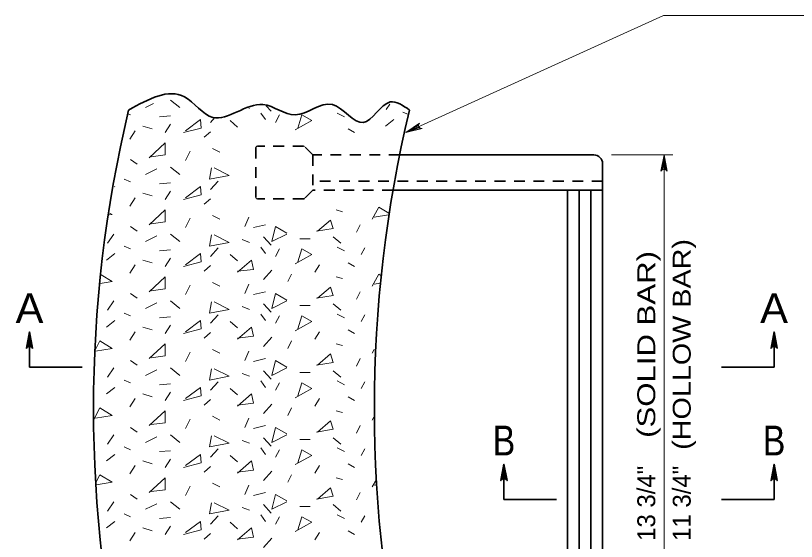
# Model space of a CAD drawing. Extents: x 16 to 133, y -56 to 112.
# Drawn here: x 17.77 to 62.26, y 81.71 to 111.64 of the extents above; entities that cross this region are included whole.
import ezdxf
from ezdxf.enums import TextEntityAlignment as Align

# ---------------------------------------------------------------- set-up
doc = ezdxf.new("R2010")
doc.units = 0
doc.header["$LTSCALE"] = 0.41
doc.linetypes.add('SHORT_DASHED', pattern=[2.7, 1.5, -1.2])
for name, color, linetype, lineweight in [('1', 7, 'Continuous', 35), ('10', 7, 'Continuous', 13), ('12', 7, 'Continuous', 53), ('13', 7, 'Continuous', 25), ('6', 7, 'Continuous', 13)]:
    doc.layers.add(name, color=color, linetype=linetype, lineweight=lineweight)

msp = doc.modelspace()

# ---------------------------------------------------------------- linework, layer by layer
at = {"layer": '1', "linetype": 'SHORT_DASHED'}
for p, q in [((31.4632, 104.126), (31.4632, 101.2927)), ((34.1786, 104.2094), (31.5465, 104.2094)), ((34.7132, 103.7094), (34.2376, 104.185)), ((34.7132, 103.7094), (34.7132, 101.7094)), ((39.651, 103.7094), (34.7132, 103.7094)), ((51.2132, 102.2094), (34.7132, 102.2094)), ((34.7132, 101.7094), (34.2376, 101.2338)), ((39.2776, 101.7094), (34.7132, 101.7094)), ((34.1786, 101.2094), (31.5465, 101.2094))]:
    msp.add_line(p, q, dxfattribs=at)
at = {"layer": '1'}
for p, q in [((50.7132, 103.7094), (39.651, 103.7094)), ((51.2132, 76.2094), (51.2132, 103.2094)), ((51.2132, 101.7094), (39.2776, 101.7094)), ((49.2132, 77.7094), (49.2132, 101.7094)), ((49.8798, 77.7094), (49.8798, 101.7094)), ((50.5465, 77.7094), (50.5465, 101.7094))]:
    msp.add_line(p, q, dxfattribs=at)
for centre, radius, start, end in [((95.4632, 89.267), 73.25, 166.58032, 193.41967), ((111.4632, 89.267), 73.25, 166.58032, 193.41967), ((50.7132, 103.2094), 0.5, 0, 90)]:
    msp.add_arc(centre, radius, start, end, dxfattribs=at)
at = {"layer": '1', "linetype": 'SHORT_DASHED'}
msp.add_arc((34.1787, 101.2927), 0.0833, 270, 315, dxfattribs=at)
at = {"layer": '1'}
msp.add_spline([(24.2131, 106.267), (27.3964, 107.0185), (29.0086, 105.8453), (31.8666, 106.5785), (33.6986, 105.9919), (35.8238, 106.5785), (37.5826, 105.552), (39.1216, 106.7252), (40.2131, 106.267)], degree=3, dxfattribs=at)
at = {"layer": '10'}
for p, q in [((54.6853, 111.6433), (40.0105, 104.9805)), ((67.387, 111.6433), (54.6853, 111.6433)), ((51.7132, 103.7094), (55.2132, 103.7094)), ((54.7132, 75.7094), (54.7132, 103.7094))]:
    msp.add_line(p, q, dxfattribs=at)
at = {"layer": '10', "lineweight": 35}
for p, q in [((60.9837, 91.6335), (60.9837, 93.6335)), ((57.9837, 91.6335), (60.9837, 91.6335))]:
    msp.add_line(p, q, dxfattribs=at)
at = {"layer": '10'}
for points in [[(40.0105, 104.9805), (40.7869, 105.5249), (40.7421, 105.4499), (40.7342, 105.3777), (40.7503, 105.3164), (40.7859, 105.2639), (40.8455, 105.2223), (40.9314, 105.2067), (40.0105, 104.9805), (40.8455, 105.2223), (40.7859, 105.2639), (40.0105, 104.9805), (40.7503, 105.3164), (40.7342, 105.3777), (40.0105, 104.9805), (40.7421, 105.4499)], [(54.7132, 103.7094), (54.8879, 102.7773), (54.8382, 102.8491), (54.7757, 102.8861), (54.7132, 102.8969), (54.6507, 102.8861), (54.5882, 102.8491), (54.5384, 102.7773), (54.7132, 103.7094), (54.5882, 102.8491), (54.6507, 102.8861), (54.7132, 103.7094), (54.7132, 102.8969), (54.7757, 102.8861), (54.7132, 103.7094), (54.8382, 102.8491)]]:
    msp.add_lwpolyline(points, dxfattribs=at)
at = {"layer": '10', "lineweight": 35}
for points in [[(18.5662, 93.6335), (18.3915, 92.7014), (18.4412, 92.7733), (18.5037, 92.8103), (18.5662, 92.821), (18.6287, 92.8103), (18.6912, 92.7733), (18.741, 92.7014), (18.5662, 93.6335), (18.6912, 92.7733), (18.6287, 92.8103), (18.5662, 93.6335), (18.5662, 92.821), (18.5037, 92.8103), (18.5662, 93.6335), (18.4412, 92.7733)], [(21.5662, 91.6335), (18.5662, 91.6335), (18.5662, 93.6335)], [(60.9837, 93.6335), (61.1585, 92.7014), (61.1087, 92.7733), (61.0462, 92.8103), (60.9837, 92.821), (60.9212, 92.8103), (60.8587, 92.7733), (60.809, 92.7014), (60.9837, 93.6335), (60.8587, 92.7733), (60.9212, 92.8103), (60.9837, 93.6335), (60.9837, 92.821), (61.0462, 92.8103), (60.9837, 93.6335), (61.1087, 92.7733)], [(45.5961, 86.0975), (45.4214, 85.1654), (45.4711, 85.2373), (45.5336, 85.2743), (45.5961, 85.285), (45.6586, 85.2743), (45.7211, 85.2373), (45.7709, 85.1654), (45.5961, 86.0975), (45.7211, 85.2373), (45.6586, 85.2743), (45.5961, 86.0975), (45.5961, 85.285), (45.5336, 85.2743), (45.5961, 86.0975), (45.4711, 85.2373)], [(48.5961, 84.0975), (45.5961, 84.0975), (45.5961, 86.0975)], [(57.9837, 84.0975), (60.9837, 84.0975), (60.9837, 86.0975)], [(60.9837, 86.0975), (61.1585, 85.1654), (61.1087, 85.2373), (61.0462, 85.2743), (60.9837, 85.285), (60.9212, 85.2743), (60.8587, 85.2373), (60.809, 85.1654), (60.9837, 86.0975), (60.8587, 85.2373), (60.9212, 85.2743), (60.9837, 86.0975), (60.9837, 85.285), (61.0462, 85.2743), (60.9837, 86.0975), (61.1087, 85.2373)]]:
    msp.add_lwpolyline(points, dxfattribs=at)
at = {"layer": '6'}
for p, q in [((26.6059, 106.8326), (27.1354, 106.409)), ((25.6384, 106.6401), (25.1762, 106.409)), ((31.0526, 106.3764), (31.1067, 106.3561)), ((32.0547, 106.5009), (32.3246, 106.1972)), ((36.1245, 106.4531), (36.296, 106.3031)), ((36.1245, 106.4531), (36.1245, 106.4531)), ((39.0999, 106.6021), (38.8906, 106.3031)), ((24.1736, 106.052), (24.329, 105.9854)), ((25.9704, 105.8795), (26.6059, 105.9325)), ((31.7421, 106.0913), (32.0069, 105.7207)), ((32.8012, 105.9854), (32.5894, 105.5618)), ((36.0841, 106.0913), (36.5078, 105.8795)), ((39.8437, 106.1443), (40.1567, 106.0101)), ((26.2881, 104.9793), (26.6059, 105.4559)), ((28.8828, 105.5618), (29.129, 105.8388)), ((29.9947, 105.6677), (30.4184, 105.2971)), ((39.3142, 105.7207), (38.8376, 105.35)), ((24.5937, 105.0852), (24.276, 104.6087)), ((25.0173, 105.35), (25.5468, 105.1911)), ((28.5121, 104.7146), (28.8828, 105.0323)), ((36.7196, 105.1911), (37.0902, 104.9793)), ((27.4531, 103.3908), (27.7178, 103.9203)), ((28.9887, 104.0792), (29.4123, 103.8674)), ((24.329, 103.4437), (24.6996, 103.179)), ((25.8116, 102.9142), (25.1762, 102.5965)), ((26.6059, 103.0201), (27.1354, 102.5965)), ((23.9583, 102.3318), (24.329, 102.1729)), ((23.4288, 101.9082), (23.4074, 101.8915)), ((25.9704, 102.067), (26.6059, 102.12)), ((28.8828, 101.7493), (29.3064, 102.2259)), ((25.0173, 101.5375), (25.5468, 101.3786)), ((26.2881, 101.1668), (26.6059, 101.6434)), ((24.5937, 101.2727), (24.276, 100.7962)), ((28.5121, 100.9021), (28.8828, 101.2198)), ((36.0312, 100.5844), (36.4019, 100.4785)), ((27.4531, 99.5783), (27.7178, 100.1078)), ((28.9887, 100.2667), (29.4123, 100.0549)), ((31.0538, 100.1608), (30.842, 99.6312)), ((39.0151, 100.2962), (38.2022, 100.1608)), ((32.0069, 99.7372), (31.3185, 99.5783)), ((37.1961, 99.3135), (37.4079, 99.7372)), ((23.3758, 99.2076), (23.0052, 98.6781)), ((24.329, 99.6312), (24.6996, 99.3665)), ((26.6059, 99.2076), (27.1354, 98.784)), ((25.8116, 99.1017), (25.1762, 98.784)), ((30.6831, 98.8899), (31.1067, 98.7311)), ((31.901, 99.0488), (32.3246, 98.5722)), ((33.9661, 98.9429), (34.5486, 98.9429)), ((35.8724, 99.0488), (36.296, 98.6781)), ((23.9583, 98.5193), (24.329, 98.3604)), ((25.9704, 98.2545), (26.6059, 98.3075)), ((28.8828, 97.9368), (29.3064, 98.4134)), ((31.7421, 98.4663), (32.0069, 98.0957)), ((32.8012, 98.3604), (32.5894, 97.9368)), ((36.0841, 98.4663), (36.5078, 98.2545)), ((37.4609, 98.0427), (37.6727, 98.4134)), ((23.4288, 98.0957), (22.9522, 97.725)), ((29.9947, 98.0427), (30.4184, 97.6721)), ((24.5937, 97.4602), (24.276, 96.9837)), ((25.0173, 97.725), (25.5468, 97.5661)), ((26.2881, 97.3543), (26.6059, 97.8309)), ((34.8133, 97.0366), (35.0781, 97.4602)), ((36.7196, 97.5661), (37.0902, 97.3543)), ((28.5121, 97.0896), (28.8828, 97.4073)), ((32.3776, 97.1425), (31.901, 96.613)), ((33.4895, 96.9307), (33.2777, 96.5071)), ((36.0312, 96.7719), (36.4019, 96.666)), ((27.4531, 95.7658), (27.7178, 96.2953)), ((28.9887, 96.4542), (29.4123, 96.2424)), ((31.0538, 96.3483), (30.842, 95.8187)), ((38.5482, 96.4059), (38.2022, 96.3483)), ((24.329, 95.8187), (24.6996, 95.554)), ((32.0069, 95.9247), (31.3185, 95.7658)), ((37.1961, 95.501), (37.4079, 95.9247)), ((23.3758, 95.3951), (23.0052, 94.8656)), ((25.8116, 95.2892), (25.1762, 94.9715)), ((26.6059, 95.3951), (27.1354, 94.9715)), ((31.901, 95.2363), (32.3246, 94.7597)), ((35.8724, 95.2363), (36.296, 94.8656)), ((30.6831, 95.0774), (31.1067, 94.9186)), ((33.9661, 95.1304), (34.5486, 95.1304)), ((23.9583, 94.7068), (24.329, 94.5479)), ((25.9704, 94.442), (26.6059, 94.495)), ((28.8828, 94.1243), (29.3064, 94.6009)), ((31.7421, 94.6538), (32.0069, 94.2832)), ((32.8012, 94.5479), (32.5894, 94.1243)), ((36.0841, 94.6538), (36.5078, 94.442)), ((37.4609, 94.2302), (37.6727, 94.6009)), ((23.4288, 94.2832), (22.9522, 93.9125)), ((25.0173, 93.9125), (25.5468, 93.7536)), ((26.2881, 93.5418), (26.6059, 94.0184)), ((29.9947, 94.2302), (30.4184, 93.8596)), ((24.5937, 93.6477), (24.276, 93.1712)), ((28.5121, 93.2771), (28.8828, 93.5948)), ((34.8133, 93.2241), (35.0781, 93.6477)), ((36.7196, 93.7536), (37.0902, 93.5418)), ((32.3776, 93.33), (31.901, 92.8005)), ((33.4895, 93.1182), (33.2777, 92.6946)), ((28.9887, 92.6417), (29.4123, 92.4299)), ((31.0538, 92.5358), (30.842, 92.0062)), ((36.0312, 92.9594), (36.4019, 92.8535)), ((38.0963, 92.4299), (38.202, 92.6261)), ((27.4531, 91.9533), (27.7178, 92.4828)), ((32.0069, 92.1122), (31.3185, 91.9533)), ((37.1961, 91.6885), (37.4079, 92.1122)), ((24.329, 92.0062), (24.6996, 91.7415)), ((23.3758, 91.5826), (23.0052, 91.0531)), ((25.8116, 91.4767), (25.1762, 91.159)), ((26.6059, 91.5826), (27.1354, 91.159)), ((30.6831, 91.2649), (31.1067, 91.1061)), ((31.901, 91.4238), (32.3246, 90.9472)), ((33.9661, 91.3179), (34.5486, 91.3179)), ((35.8724, 91.4238), (36.296, 91.0531)), ((23.9583, 90.8943), (24.329, 90.7354)), ((28.8828, 90.3118), (29.3064, 90.7884)), ((31.7421, 90.8413), (32.0069, 90.4707)), ((36.0841, 90.8413), (36.5078, 90.6295)), ((37.4609, 90.4177), (37.6727, 90.7884)), ((23.4288, 90.4707), (22.9522, 90.1)), ((25.9704, 90.6295), (26.6059, 90.6825)), ((29.9947, 90.4177), (30.4184, 90.0471)), ((32.8012, 90.7354), (32.5894, 90.3118)), ((25.0173, 90.1), (25.5468, 89.9411)), ((26.2881, 89.7293), (26.6059, 90.2059)), ((36.7196, 89.9411), (37.0902, 89.7293)), ((24.5937, 89.8352), (24.276, 89.3587)), ((28.5121, 89.4646), (28.8828, 89.7823)), ((32.3776, 89.5175), (31.901, 88.988)), ((34.8133, 89.4116), (35.0781, 89.8352)), ((33.4895, 89.3057), (33.2777, 88.8821)), ((36.0312, 89.1469), (36.4019, 89.041)), ((27.4531, 88.1408), (27.7178, 88.6703)), ((28.9887, 88.8292), (29.4123, 88.6174)), ((31.0538, 88.7233), (30.842, 88.1937)), ((38.0963, 88.6174), (38.1818, 88.776)), ((24.329, 88.1937), (24.6996, 87.929)), ((32.0069, 88.2997), (31.3185, 88.1408)), ((37.1961, 87.876), (37.4079, 88.2997)), ((23.3758, 87.7701), (23.0052, 87.2406)), ((25.8116, 87.6642), (25.1762, 87.3465)), ((26.6059, 87.7701), (27.1354, 87.3465)), ((30.6831, 87.4524), (31.1067, 87.2936)), ((31.901, 87.6113), (32.3246, 87.1347)), ((33.9661, 87.5054), (34.5486, 87.5054)), ((35.8724, 87.6113), (36.296, 87.2406)), ((23.9583, 87.0818), (24.329, 86.9229)), ((25.9704, 86.817), (26.6059, 86.87)), ((28.8828, 86.4993), (29.3064, 86.9759)), ((31.7421, 87.0288), (32.0069, 86.6582)), ((32.8012, 86.9229), (32.5894, 86.4993)), ((36.0841, 87.0288), (36.5078, 86.817)), ((37.4609, 86.6052), (37.6727, 86.9759)), ((23.4288, 86.6582), (22.9522, 86.2875)), ((26.2881, 85.9168), (26.6059, 86.3934)), ((29.9947, 86.6052), (30.4184, 86.2346)), ((24.5937, 86.0227), (24.276, 85.5462)), ((25.0173, 86.2875), (25.5468, 86.1286)), ((28.5121, 85.6521), (28.8828, 85.9698)), ((34.8133, 85.5991), (35.0781, 86.0227)), ((36.7196, 86.1286), (37.0902, 85.9168)), ((32.3776, 85.705), (31.901, 85.1755)), ((33.4895, 85.4932), (33.2777, 85.0696)), ((28.9887, 85.0167), (29.4123, 84.8049)), ((36.0312, 85.3344), (36.4019, 85.2285)), ((38.0963, 84.8049), (38.3291, 85.2372)), ((27.4531, 84.3283), (27.7178, 84.8578)), ((31.0538, 84.9108), (30.842, 84.3812)), ((38.3472, 84.9349), (38.2022, 84.9108)), ((24.329, 84.3812), (24.6996, 84.1165)), ((32.0069, 84.4872), (31.3185, 84.3283)), ((37.1961, 84.0635), (37.4079, 84.4872)), ((23.3758, 83.9576), (23.0052, 83.4281)), ((25.8116, 83.8517), (25.1762, 83.534)), ((26.6059, 83.9576), (27.1354, 83.534)), ((30.6831, 83.6399), (31.1067, 83.4811)), ((31.901, 83.7988), (32.3246, 83.3222)), ((33.9661, 83.6929), (34.5486, 83.6929)), ((35.8724, 83.7988), (36.296, 83.4281)), ((23.9583, 83.2693), (24.329, 83.1104)), ((31.7421, 83.2163), (32.0069, 82.8457)), ((36.0841, 83.2163), (36.5078, 83.0045)), ((23.4288, 82.8457), (22.9522, 82.475)), ((25.9704, 83.0045), (26.6059, 83.0575)), ((28.8828, 82.6868), (29.3064, 83.1634)), ((29.9947, 82.7927), (30.4184, 82.4221)), ((32.8012, 83.1104), (32.5894, 82.6868)), ((37.4609, 82.7927), (37.6727, 83.1634)), ((25.0173, 82.475), (25.5468, 82.3161)), ((26.2881, 82.1043), (26.6059, 82.5809)), ((36.7196, 82.3161), (37.0902, 82.1043)), ((24.5937, 82.2102), (24.276, 81.7337)), ((28.5121, 81.8396), (28.8828, 82.1573)), ((32.3776, 81.8925), (31.901, 81.363)), ((34.8133, 81.7866), (35.0781, 82.2102))]:
    msp.add_line(p, q, dxfattribs=at)
for points in [[(33.7013, 105.1382), (34.6545, 105.6677), (34.072, 105.9854), (33.8602, 105.2441)], [(27.3472, 104.9793), (28.3532, 105.2441), (28.3003, 105.7207), (27.4531, 105.0852)], [(25.4939, 103.6026), (26.2881, 103.7085), (26.2881, 104.3969), (25.388, 103.5497)], [(28.9357, 102.9672), (28.8298, 102.3318), (29.9418, 102.5436), (29.0946, 102.9672)], [(27.3472, 101.1668), (28.3532, 101.4316), (28.3003, 101.9082), (27.4531, 101.2727)], [(25.4939, 99.7901), (26.2881, 99.896), (26.2881, 100.5844), (25.388, 99.7372)], [(38.0963, 100.0549), (38.467, 100.7432), (39.0334, 100.3947)], [(23.1334, 100.4036), (23.2699, 100.3196), (23.1131, 100.2935)], [(34.9192, 99.3665), (35.8724, 99.5253), (35.7135, 100.0019), (34.9722, 99.3665)], [(33.2248, 99.2076), (32.3776, 98.784), (32.5894, 99.6312), (33.2248, 99.2606)], [(28.9357, 99.1547), (28.8298, 98.5193), (29.9418, 98.7311), (29.0946, 99.1547)], [(33.7013, 97.5132), (34.6545, 98.0427), (34.072, 98.3604), (33.8602, 97.6191)], [(27.3472, 97.3543), (28.3532, 97.6191), (28.3003, 98.0957), (27.4531, 97.4602)], [(30.4184, 97.0896), (31.3185, 97.1955), (31.2126, 97.725), (30.4184, 97.0366)], [(22.6488, 96.8893), (23.2699, 96.5071), (22.5965, 96.3949)], [(25.4939, 95.9776), (26.2881, 96.0835), (26.2881, 96.7719), (25.388, 95.9247)], [(38.0963, 96.2424), (38.467, 96.9307), (38.5899, 96.8551)], [(34.9192, 95.554), (35.8724, 95.7128), (35.7135, 96.1894), (34.9722, 95.554)], [(33.2248, 95.3951), (32.3776, 94.9715), (32.5894, 95.8187), (33.2248, 95.4481)], [(28.9357, 95.3422), (28.8298, 94.7068), (29.9418, 94.9186), (29.0946, 95.3422)], [(33.7013, 93.7007), (34.6545, 94.2302), (34.072, 94.5479), (33.8602, 93.8066)], [(27.3472, 93.5418), (28.3532, 93.8066), (28.3003, 94.2832), (27.4531, 93.6477)], [(30.4184, 93.2771), (31.3185, 93.383), (31.2126, 93.9125), (30.4184, 93.2241)], [(22.2604, 92.5219), (22.5816, 93.1182), (23.2699, 92.6946), (22.3168, 92.5358)], [(25.4939, 92.1651), (26.2881, 92.271), (26.2881, 92.9594), (25.388, 92.1122)], [(34.9192, 91.7415), (35.8724, 91.9003), (35.7135, 92.3769), (34.9722, 91.7415)], [(33.2248, 91.5826), (32.3776, 91.159), (32.5894, 92.0062), (33.2248, 91.6356)], [(28.9357, 91.5297), (28.8298, 90.8943), (29.9418, 91.1061), (29.0946, 91.5297)], [(27.3472, 89.7293), (28.3532, 89.9941), (28.3003, 90.4707), (27.4531, 89.8352)], [(33.7013, 89.8882), (34.6545, 90.4177), (34.072, 90.7354), (33.8602, 89.9941)], [(30.4184, 89.4646), (31.3185, 89.5705), (31.2126, 90.1), (30.4184, 89.4116)], [(22.2109, 88.6174), (22.5816, 89.3057), (23.2699, 88.8821), (22.3168, 88.7233)], [(25.4939, 88.3526), (26.2881, 88.4585), (26.2881, 89.1469), (25.388, 88.2997)], [(34.9192, 87.929), (35.8724, 88.0878), (35.7135, 88.5644), (34.9722, 87.929)], [(33.2248, 87.7701), (32.3776, 87.3465), (32.5894, 88.1937), (33.2248, 87.8231)], [(28.9357, 87.7172), (28.8298, 87.0818), (29.9418, 87.2936), (29.0946, 87.7172)], [(33.7013, 86.0757), (34.6545, 86.6052), (34.072, 86.9229), (33.8602, 86.1816)], [(27.3472, 85.9168), (28.3532, 86.1816), (28.3003, 86.6582), (27.4531, 86.0227)], [(30.4184, 85.6521), (31.3185, 85.758), (31.2126, 86.2875), (30.4184, 85.5991)], [(22.3462, 85.0561), (22.5816, 85.4932), (23.2699, 85.0696), (22.3602, 84.918)], [(25.4939, 84.5401), (26.2881, 84.646), (26.2881, 85.3344), (25.388, 84.4872)], [(34.9192, 84.1165), (35.8724, 84.2753), (35.7135, 84.7519), (34.9722, 84.1165)], [(33.2248, 83.9576), (32.3776, 83.534), (32.5894, 84.3812), (33.2248, 84.0106)], [(28.9357, 83.9047), (28.8298, 83.2693), (29.9418, 83.4811), (29.0946, 83.9047)], [(27.3472, 82.1043), (28.3532, 82.3691), (28.3003, 82.8457), (27.4531, 82.2102)], [(33.7013, 82.2632), (34.6545, 82.7927), (34.072, 83.1104), (33.8602, 82.3691)], [(30.4184, 81.8396), (31.3185, 81.9455), (31.2126, 82.475), (30.4184, 81.7866)]]:
    msp.add_lwpolyline(points, dxfattribs=at)
at = {"layer": '6', "linetype": 'SHORT_DASHED'}
for centre, start, end in [((31.5465, 104.126), 90, 180), ((34.1787, 104.126), 45, 90), ((31.5465, 101.2927), 180, 270)]:
    msp.add_arc(centre, 0.0833, start, end, dxfattribs=at)

# ---------------------------------------------------------------- texts
at = {"layer": '12'}
for s, width, p in [('(HOLLOW BAR)', 1.2, (56.2332, 92.9213)), ('(SOLID BAR)', 1.3, (54.2132, 92.9213))]:
    msp.add_text(s, height=1.02, rotation=90, dxfattribs=dict(at, width=width)).set_placement(p, align=Align.CENTER)
for s, width, p in [('A', 1.05, (18.5662, 94.1335)), ('A', 1.05, (60.9837, 94.1335)), ('B', 0.85, (45.5961, 86.5975)), ('B', 0.85, (60.9837, 86.5975))]:
    msp.add_text(s, height=1.7, dxfattribs=dict(at, width=width)).set_placement(p, align=Align.CENTER)
at = {"layer": '13'}
for s, p in [('13 3/4"', (54.2132, 83.8733)), ('11 3/4"', (56.2332, 83.8733))]:
    msp.add_text(s, height=1.02, rotation=90, dxfattribs=at).set_placement(p, align=Align.CENTER)

doc.saveas('drawing.dxf')
